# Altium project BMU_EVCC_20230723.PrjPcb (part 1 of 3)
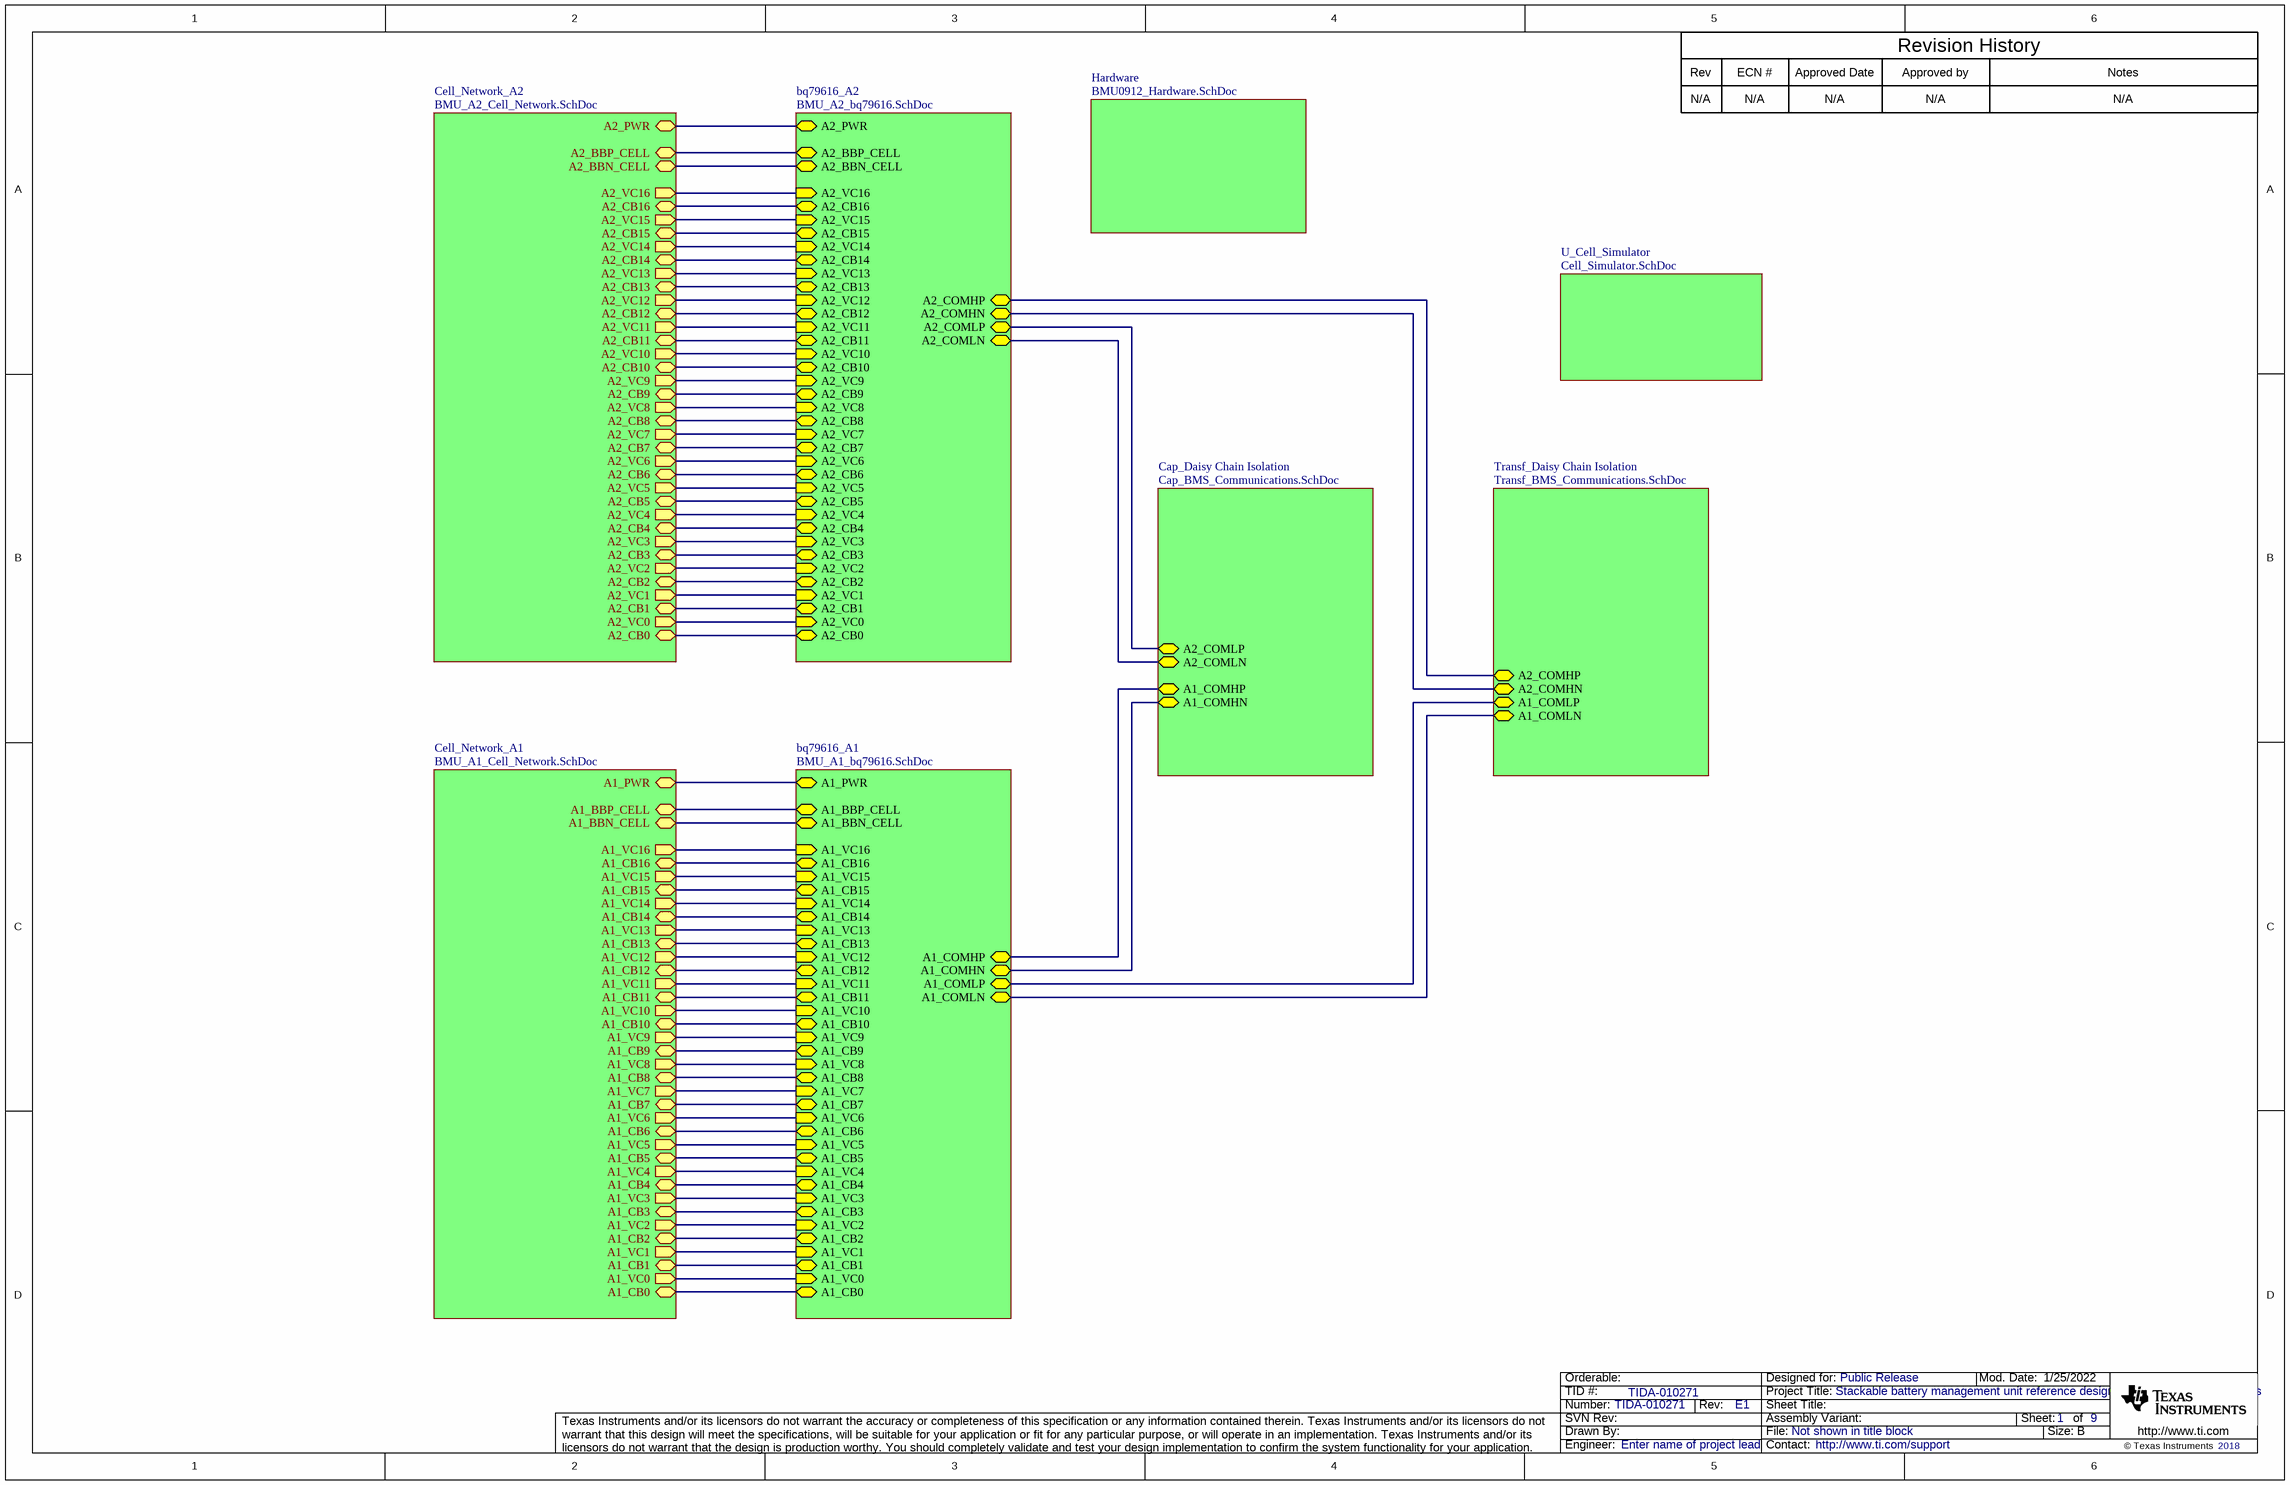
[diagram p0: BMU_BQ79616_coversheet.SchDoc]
CopyrightYear: 2018; PCB_Layout: Junhua Yan; PCB_Rev: E1; PRJ_Customer: Public Release; PRJ_Engineer: Enter name of project lead; PRJ_Number: TIDA-010271; PRJ_Title: Stackable battery management unit reference design for energy storage systems; SCH_Rev: E1; TechSupport: http://www.ti.com/support; TID: TIDA-010271
9 sheets, 713 parts. Net scope: hierarchical (ports join the sheet entries above them; power ports are global).
Board file: BMU_BQ79616.PcbDoc
Sheets:
  BMU_BQ79616_coversheet.SchDoc
    Cell_Network_A2 = BMU_A2_Cell_Network.SchDoc
    bq79616_A2 = BMU_A2_bq79616.SchDoc
    Transf_Daisy Chain Isolation = Transf_BMS_Communications.SchDoc
    Cap_Daisy Chain Isolation = Cap_BMS_Communications.SchDoc
    Cell_Network_A1 = BMU_A1_Cell_Network.SchDoc
    bq79616_A1 = BMU_A1_bq79616.SchDoc
    Hardware = BMU0912_Hardware.SchDoc
    U_Cell_Simulator = Cell_Simulator.SchDoc

## Sheet BMU_BQ79616_coversheet.SchDoc
size 431 x 279 mm; Date: Not shown in title block; ApprovedBy: Not shown in title block; CheckedBy: Not shown in title block; Author: Not shown in title block; CompanyName: Not shown in title block; Engineer: Not shown in title block; Organization: Not shown in title block; Address1: Not shown in title block; Address2: Not shown in title block; Address3: Not shown in title block; Address4: Not shown in title block; DocumentNumber: 1; Revision: Use project parameter SCH_Rev; SheetNumber: 1; SheetTotal: 9; PageSetup: Record=PageOptions¦CenterHorizontal=True¦CenterVertical=True¦PrintScale=1.00¦XCorrection=1.00¦YCorrection=1.00¦PrintKind=0¦BorderSize=5000000¦LeftOffset=0¦BottomOffset=0¦Orientation=2¦PaperLength=1000¦PaperWidth=1000¦Scale=100¦PaperSource=15¦PrintQuality=600¦MediaType=1¦DitherType=10¦PaperKind=Letter¦PrintScaleMode=1

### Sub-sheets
bq79616_A1 = BMU_A1_bq79616.SchDoc: A1_PWR (bidir), A1_CB1 (bidir), A1_CB14 (bidir), A1_CB15 (bidir), A1_CB16 (bidir), A1_VC0 (in), A1_VC1 (in), A1_VC2 (in), A1_VC3 (in), A1_VC4 (in), A1_VC5 (in), A1_VC6 (in), A1_VC7 (in), A1_VC8 (in), A1_VC9 (in), A1_VC10 (in), A1_VC11 (in), A1_VC12 (in), A1_VC13 (in), A1_VC14 (in), A1_VC15 (in), A1_VC16 (in), A1_CB2 (bidir), A1_CB3 (bidir), A1_CB4 (bidir), A1_CB5 (bidir), A1_CB6 (bidir), A1_CB7 (bidir), A1_CB8 (bidir), A1_CB9 (bidir), A1_CB10 (bidir), A1_CB11 (bidir), A1_CB12 (bidir), A1_CB13 (bidir), A1_COMLN (bidir), A1_COMLP (bidir), A1_COMHN (bidir), A1_COMHP (bidir), A1_CB0 (bidir), A1_BBP_CELL (bidir), A1_BBN_CELL (bidir)
bq79616_A2 = BMU_A2_bq79616.SchDoc: A2_PWR (bidir), A2_CB1 (bidir), A2_CB14 (bidir), A2_CB15 (bidir), A2_CB16 (bidir), A2_VC0 (in), A2_VC1 (in), A2_VC2 (in), A2_VC3 (in), A2_VC4 (in), A2_VC5 (in), A2_VC6 (in), A2_VC7 (in), A2_VC8 (in), A2_VC9 (in), A2_VC10 (in), A2_VC11 (in), A2_VC12 (in), A2_VC13 (in), A2_VC14 (in), A2_VC15 (in), A2_VC16 (in), A2_CB2 (bidir), A2_CB3 (bidir), A2_CB4 (bidir), A2_CB5 (bidir), A2_CB6 (bidir), A2_CB7 (bidir), A2_CB8 (bidir), A2_CB9 (bidir), A2_CB10 (bidir), A2_CB11 (bidir), A2_CB12 (bidir), A2_CB13 (bidir), A2_COMLN (bidir), A2_COMLP (bidir), A2_COMHN (bidir), A2_COMHP (bidir), A2_CB0 (bidir), A2_BBP_CELL (bidir), A2_BBN_CELL (bidir)
Cap_Daisy Chain Isolation = Cap_BMS_Communications.SchDoc: A2_COMLP (bidir), A1_COMHN (bidir), A2_COMLN (bidir), A1_COMHP (bidir)
Cell_Network_A1 = BMU_A1_Cell_Network.SchDoc: A1_PWR (bidir), A1_VC16 (out), A1_CB16 (bidir), A1_VC15 (out), A1_CB15 (bidir), A1_VC14 (out), A1_CB14 (bidir), A1_VC13 (out), A1_CB13 (bidir), A1_VC12 (out), A1_CB12 (bidir), A1_VC11 (out), A1_CB11 (bidir), A1_VC10 (out), A1_CB10 (bidir), A1_VC9 (out), A1_CB9 (bidir), A1_VC8 (out), A1_CB8 (bidir), A1_VC7 (out), A1_CB7 (bidir), A1_VC6 (out), A1_CB6 (bidir), A1_VC5 (out), A1_CB5 (bidir), A1_VC4 (out), A1_CB4 (bidir), A1_VC3 (out), A1_CB3 (bidir), A1_VC2 (out), A1_CB2 (bidir), A1_VC1 (out), A1_CB1 (bidir), A1_VC0 (out), A1_CB0 (bidir), A1_BBN_CELL (bidir), A1_BBP_CELL (bidir)
Cell_Network_A2 = BMU_A2_Cell_Network.SchDoc: A2_PWR (bidir), A2_VC16 (out), A2_CB16 (bidir), A2_VC15 (out), A2_CB15 (bidir), A2_VC14 (out), A2_CB14 (bidir), A2_VC13 (out), A2_CB13 (bidir), A2_VC12 (out), A2_CB12 (bidir), A2_VC11 (out), A2_CB11 (bidir), A2_VC10 (out), A2_CB10 (bidir), A2_VC9 (out), A2_CB9 (bidir), A2_VC8 (out), A2_CB8 (bidir), A2_VC7 (out), A2_CB7 (bidir), A2_VC6 (out), A2_CB6 (bidir), A2_VC5 (out), A2_CB5 (bidir), A2_VC4 (out), A2_CB4 (bidir), A2_VC3 (out), A2_CB3 (bidir), A2_VC2 (out), A2_CB2 (bidir), A2_VC1 (out), A2_CB1 (bidir), A2_VC0 (out), A2_CB0 (bidir), A2_BBP_CELL (bidir), A2_BBN_CELL (bidir)
Hardware = BMU0912_Hardware.SchDoc: no entries
Transf_Daisy Chain Isolation = Transf_BMS_Communications.SchDoc: A1_COMLP (bidir), A2_COMHN (bidir), A1_COMLN (bidir), A2_COMHP (bidir)
U_Cell_Simulator = Cell_Simulator.SchDoc: no entries

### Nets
A1_BBN_CELL: sheet Cell_Network_A1/A1_BBN_CELL, sheet bq79616_A1/A1_BBN_CELL
A1_BBP_CELL: sheet Cell_Network_A1/A1_BBP_CELL, sheet bq79616_A1/A1_BBP_CELL
A1_CB0: sheet Cell_Network_A1/A1_CB0, sheet bq79616_A1/A1_CB0
A1_CB1: sheet Cell_Network_A1/A1_CB1, sheet bq79616_A1/A1_CB1
A1_CB2: sheet Cell_Network_A1/A1_CB2, sheet bq79616_A1/A1_CB2
A1_CB3: sheet Cell_Network_A1/A1_CB3, sheet bq79616_A1/A1_CB3
A1_CB4: sheet Cell_Network_A1/A1_CB4, sheet bq79616_A1/A1_CB4
A1_CB5: sheet Cell_Network_A1/A1_CB5, sheet bq79616_A1/A1_CB5
A1_CB6: sheet Cell_Network_A1/A1_CB6, sheet bq79616_A1/A1_CB6
A1_CB7: sheet Cell_Network_A1/A1_CB7, sheet bq79616_A1/A1_CB7
A1_CB8: sheet Cell_Network_A1/A1_CB8, sheet bq79616_A1/A1_CB8
A1_CB9: sheet Cell_Network_A1/A1_CB9, sheet bq79616_A1/A1_CB9
A1_CB10: sheet Cell_Network_A1/A1_CB10, sheet bq79616_A1/A1_CB10
A1_CB11: sheet Cell_Network_A1/A1_CB11, sheet bq79616_A1/A1_CB11
A1_CB12: sheet Cell_Network_A1/A1_CB12, sheet bq79616_A1/A1_CB12
A1_CB13: sheet Cell_Network_A1/A1_CB13, sheet bq79616_A1/A1_CB13
A1_CB14: sheet Cell_Network_A1/A1_CB14, sheet bq79616_A1/A1_CB14
A1_CB15: sheet Cell_Network_A1/A1_CB15, sheet bq79616_A1/A1_CB15
A1_CB16: sheet Cell_Network_A1/A1_CB16, sheet bq79616_A1/A1_CB16
A1_COMHN: sheet Cap_Daisy Chain Isolation/A1_COMHN, sheet bq79616_A1/A1_COMHN
A1_COMHP: sheet Cap_Daisy Chain Isolation/A1_COMHP, sheet bq79616_A1/A1_COMHP
A1_COMLN: sheet Transf_Daisy Chain Isolation/A1_COMLN, sheet bq79616_A1/A1_COMLN
A1_COMLP: sheet Transf_Daisy Chain Isolation/A1_COMLP, sheet bq79616_A1/A1_COMLP
A1_PWR: sheet Cell_Network_A1/A1_PWR, sheet bq79616_A1/A1_PWR
A1_VC0: sheet Cell_Network_A1/A1_VC0, sheet bq79616_A1/A1_VC0
A1_VC1: sheet Cell_Network_A1/A1_VC1, sheet bq79616_A1/A1_VC1
A1_VC2: sheet Cell_Network_A1/A1_VC2, sheet bq79616_A1/A1_VC2
A1_VC3: sheet Cell_Network_A1/A1_VC3, sheet bq79616_A1/A1_VC3
A1_VC4: sheet Cell_Network_A1/A1_VC4, sheet bq79616_A1/A1_VC4
A1_VC5: sheet Cell_Network_A1/A1_VC5, sheet bq79616_A1/A1_VC5
A1_VC6: sheet Cell_Network_A1/A1_VC6, sheet bq79616_A1/A1_VC6
A1_VC7: sheet Cell_Network_A1/A1_VC7, sheet bq79616_A1/A1_VC7
A1_VC8: sheet Cell_Network_A1/A1_VC8, sheet bq79616_A1/A1_VC8
A1_VC9: sheet Cell_Network_A1/A1_VC9, sheet bq79616_A1/A1_VC9
A1_VC10: sheet Cell_Network_A1/A1_VC10, sheet bq79616_A1/A1_VC10
A1_VC11: sheet Cell_Network_A1/A1_VC11, sheet bq79616_A1/A1_VC11
A1_VC12: sheet Cell_Network_A1/A1_VC12, sheet bq79616_A1/A1_VC12
A1_VC13: sheet Cell_Network_A1/A1_VC13, sheet bq79616_A1/A1_VC13
A1_VC14: sheet Cell_Network_A1/A1_VC14, sheet bq79616_A1/A1_VC14
A1_VC15: sheet Cell_Network_A1/A1_VC15, sheet bq79616_A1/A1_VC15
A1_VC16: sheet Cell_Network_A1/A1_VC16, sheet bq79616_A1/A1_VC16
A2_BBN_CELL: sheet Cell_Network_A2/A2_BBN_CELL, sheet bq79616_A2/A2_BBN_CELL
A2_BBP_CELL: sheet Cell_Network_A2/A2_BBP_CELL, sheet bq79616_A2/A2_BBP_CELL
A2_CB0: sheet Cell_Network_A2/A2_CB0, sheet bq79616_A2/A2_CB0
A2_CB1: sheet Cell_Network_A2/A2_CB1, sheet bq79616_A2/A2_CB1
A2_CB2: sheet Cell_Network_A2/A2_CB2, sheet bq79616_A2/A2_CB2
A2_CB3: sheet Cell_Network_A2/A2_CB3, sheet bq79616_A2/A2_CB3
A2_CB4: sheet Cell_Network_A2/A2_CB4, sheet bq79616_A2/A2_CB4
A2_CB5: sheet Cell_Network_A2/A2_CB5, sheet bq79616_A2/A2_CB5
A2_CB6: sheet Cell_Network_A2/A2_CB6, sheet bq79616_A2/A2_CB6
A2_CB7: sheet Cell_Network_A2/A2_CB7, sheet bq79616_A2/A2_CB7
A2_CB8: sheet Cell_Network_A2/A2_CB8, sheet bq79616_A2/A2_CB8
A2_CB9: sheet Cell_Network_A2/A2_CB9, sheet bq79616_A2/A2_CB9
A2_CB10: sheet Cell_Network_A2/A2_CB10, sheet bq79616_A2/A2_CB10
A2_CB11: sheet Cell_Network_A2/A2_CB11, sheet bq79616_A2/A2_CB11
A2_CB12: sheet Cell_Network_A2/A2_CB12, sheet bq79616_A2/A2_CB12
A2_CB13: sheet Cell_Network_A2/A2_CB13, sheet bq79616_A2/A2_CB13
A2_CB14: sheet Cell_Network_A2/A2_CB14, sheet bq79616_A2/A2_CB14
A2_CB15: sheet Cell_Network_A2/A2_CB15, sheet bq79616_A2/A2_CB15
A2_CB16: sheet Cell_Network_A2/A2_CB16, sheet bq79616_A2/A2_CB16
A2_COMHN: sheet bq79616_A2/A2_COMHN, sheet Transf_Daisy Chain Isolation/A2_COMHN
A2_COMHP: sheet bq79616_A2/A2_COMHP, sheet Transf_Daisy Chain Isolation/A2_COMHP
A2_COMLN: sheet bq79616_A2/A2_COMLN, sheet Cap_Daisy Chain Isolation/A2_COMLN
A2_COMLP: sheet bq79616_A2/A2_COMLP, sheet Cap_Daisy Chain Isolation/A2_COMLP
A2_PWR: sheet Cell_Network_A2/A2_PWR, sheet bq79616_A2/A2_PWR
A2_VC0: sheet Cell_Network_A2/A2_VC0, sheet bq79616_A2/A2_VC0
A2_VC1: sheet Cell_Network_A2/A2_VC1, sheet bq79616_A2/A2_VC1
A2_VC2: sheet Cell_Network_A2/A2_VC2, sheet bq79616_A2/A2_VC2
A2_VC3: sheet Cell_Network_A2/A2_VC3, sheet bq79616_A2/A2_VC3
A2_VC4: sheet Cell_Network_A2/A2_VC4, sheet bq79616_A2/A2_VC4
A2_VC5: sheet Cell_Network_A2/A2_VC5, sheet bq79616_A2/A2_VC5
A2_VC6: sheet Cell_Network_A2/A2_VC6, sheet bq79616_A2/A2_VC6
A2_VC7: sheet Cell_Network_A2/A2_VC7, sheet bq79616_A2/A2_VC7
A2_VC8: sheet Cell_Network_A2/A2_VC8, sheet bq79616_A2/A2_VC8
A2_VC9: sheet Cell_Network_A2/A2_VC9, sheet bq79616_A2/A2_VC9
A2_VC10: sheet Cell_Network_A2/A2_VC10, sheet bq79616_A2/A2_VC10
A2_VC11: sheet Cell_Network_A2/A2_VC11, sheet bq79616_A2/A2_VC11
A2_VC12: sheet Cell_Network_A2/A2_VC12, sheet bq79616_A2/A2_VC12
A2_VC13: sheet Cell_Network_A2/A2_VC13, sheet bq79616_A2/A2_VC13
A2_VC14: sheet Cell_Network_A2/A2_VC14, sheet bq79616_A2/A2_VC14
A2_VC15: sheet Cell_Network_A2/A2_VC15, sheet bq79616_A2/A2_VC15
A2_VC16: sheet Cell_Network_A2/A2_VC16, sheet bq79616_A2/A2_VC16

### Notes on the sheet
- Rev
- N/A
- ECN #
- Approved Date
- Approved by
- Revision History
- Notes

## Sheet BMU_A2_Cell_Network.SchDoc
size C; SheetNumber: 3; SheetTotal: 9
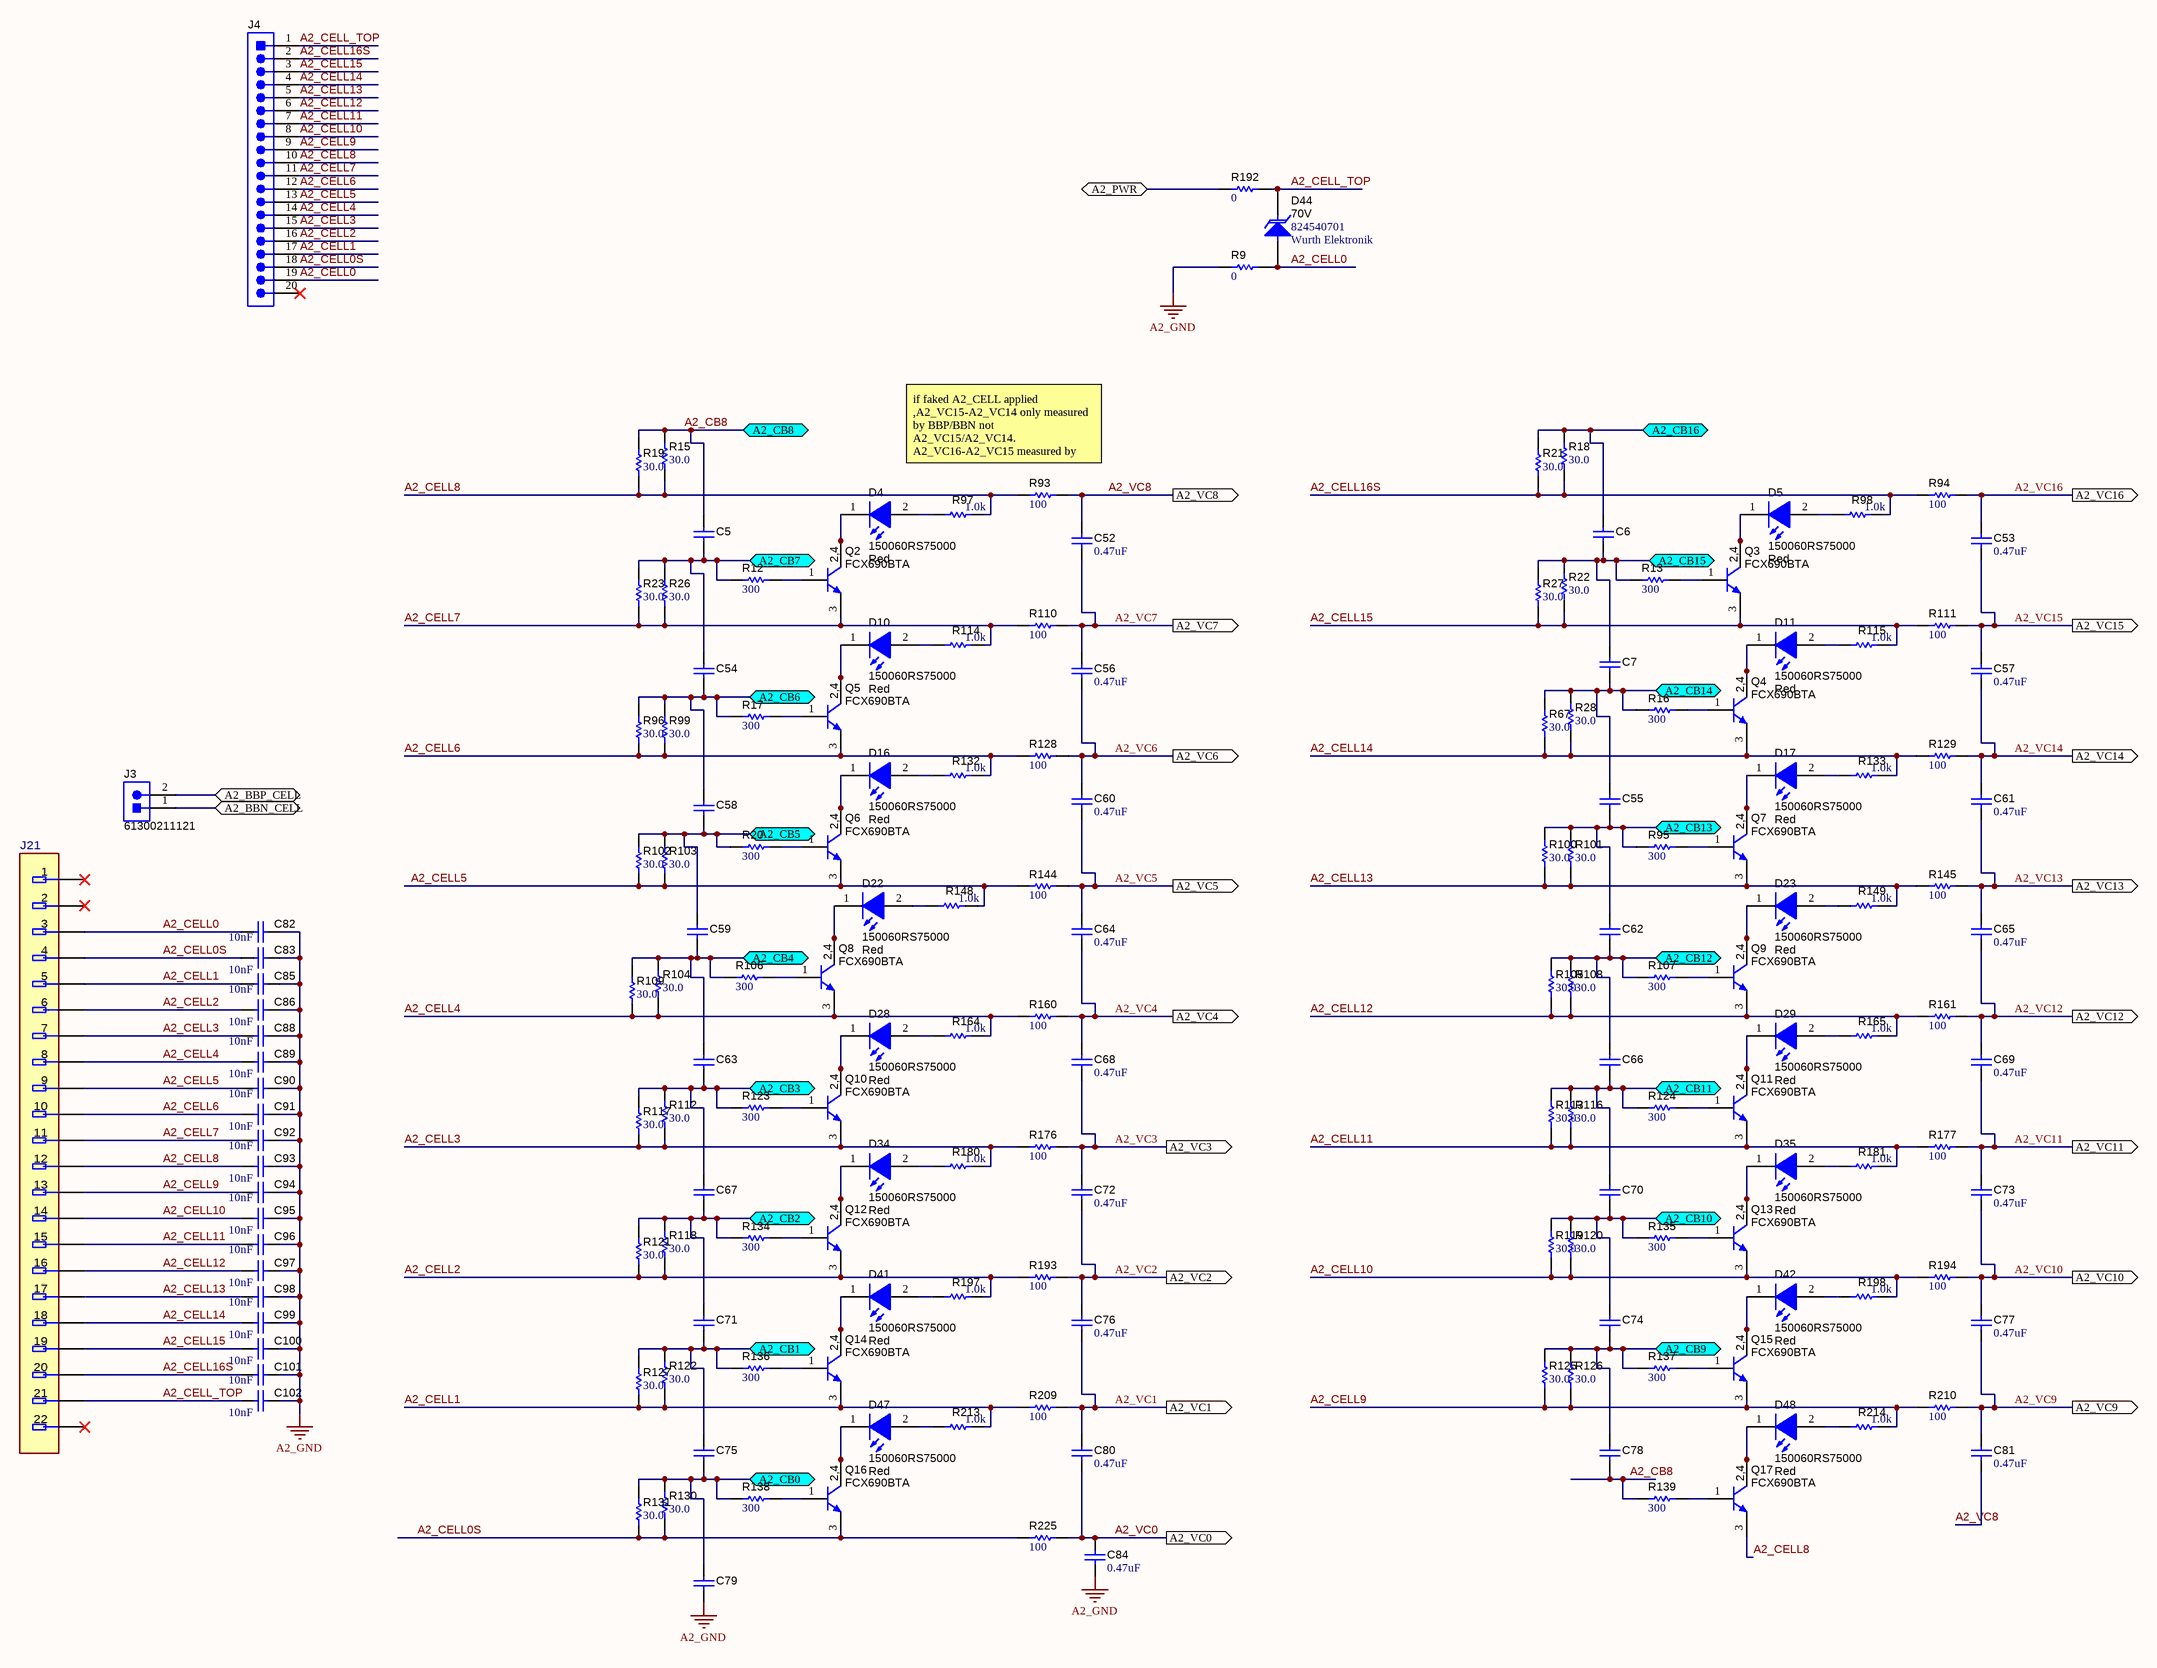
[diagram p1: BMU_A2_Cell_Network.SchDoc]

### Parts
C5  GCM188R71C474KA55D  [0603]  (value not drawn)
C6  GCM188R71C474KA55D  [0603]  (value not drawn)
C7  GCM188R71C474KA55D  [0603]  (value not drawn)
C52  ValueDisplayed: 0.47uF  [0603]  (hidden comment: GCM188R71C474KA55D)
C53  ValueDisplayed: 0.47uF  [0603]  (hidden comment: GCM188R71C474KA55D)
C54  GCM188R71C474KA55D  [0603]  (value not drawn)
C55  GCM188R71C474KA55D  [0603]  (value not drawn)
C56  ValueDisplayed: 0.47uF  [0603]  (hidden comment: GCM188R71C474KA55D)
C57  ValueDisplayed: 0.47uF  [0603]  (hidden comment: GCM188R71C474KA55D)
C58  GCM188R71C474KA55D  [0603]  (value not drawn)
C59  GCM188R71C474KA55D  [0603]  (value not drawn)
C60  ValueDisplayed: 0.47uF  [0603]  (hidden comment: GCM188R71C474KA55D)
C61  ValueDisplayed: 0.47uF  [0603]  (hidden comment: GCM188R71C474KA55D)
C62  GCM188R71C474KA55D  [0603]  (value not drawn)
C63  GCM188R71C474KA55D  [0603]  (value not drawn)
C64  ValueDisplayed: 0.47uF  [0603]  (hidden comment: GCM188R71C474KA55D)
C65  ValueDisplayed: 0.47uF  [0603]  (hidden comment: GCM188R71C474KA55D)
C66  GCM188R71C474KA55D  [0603]  (value not drawn)
C67  GCM188R71C474KA55D  [0603]  (value not drawn)
C68  ValueDisplayed: 0.47uF  [0603]  (hidden comment: GCM188R71C474KA55D)
C69  ValueDisplayed: 0.47uF  [0603]  (hidden comment: GCM188R71C474KA55D)
C70  GCM188R71C474KA55D  [0603]  (value not drawn)
C71  GCM188R71C474KA55D  [0603]  (value not drawn)
C72  ValueDisplayed: 0.47uF  [0603]  (hidden comment: GCM188R71C474KA55D)
C73  ValueDisplayed: 0.47uF  [0603]  (hidden comment: GCM188R71C474KA55D)
C74  GCM188R71C474KA55D  [0603]  (value not drawn)
C75  GCM188R71C474KA55D  [0603]  (value not drawn)
C76  ValueDisplayed: 0.47uF  [0603]  (hidden comment: GCM188R71C474KA55D)
C77  ValueDisplayed: 0.47uF  [0603]  (hidden comment: GCM188R71C474KA55D)
C78  GCM188R71C474KA55D  [0603]  (value not drawn)
C79  GCM188R71C474KA55D  [0603]  (value not drawn)
C80  ValueDisplayed: 0.47uF  [0603]  (hidden comment: GCM188R71C474KA55D)
C81  ValueDisplayed: 0.47uF  [0603]  (hidden comment: GCM188R71C474KA55D)
C82  Cap_F: 10nF  [0603]  (hidden comment: 885012206114)
C83  Cap_F: 10nF  [0603]  (hidden comment: 885012206114)
C84  ValueDisplayed: 0.47uF  [0603]  (hidden comment: GCM188R71C474KA55D)
C85  Cap_F: 10nF  [0603]  (hidden comment: 885012206114)
C86  Cap_F: 10nF  [0603]  (hidden comment: 885012206114)
C88  Cap_F: 10nF  [0603]  (hidden comment: 885012206114)
C89  Cap_F: 10nF  [0603]  (hidden comment: 885012206114)
C90  Cap_F: 10nF  [0603]  (hidden comment: 885012206114)
C91  Cap_F: 10nF  [0603]  (hidden comment: 885012206114)
C92  Cap_F: 10nF  [0603]  (hidden comment: 885012206114)
C93  Cap_F: 10nF  [0603]  (hidden comment: 885012206114)
C94  Cap_F: 10nF  [0603]  (hidden comment: 885012206114)
C95  Cap_F: 10nF  [0603]  (hidden comment: 885012206114)
C96  Cap_F: 10nF  [0603]  (hidden comment: 885012206114)
C97  Cap_F: 10nF  [0603]  (hidden comment: 885012206114)
C98  Cap_F: 10nF  [0603]  (hidden comment: 885012206114)
C99  Cap_F: 10nF  [0603]  (hidden comment: 885012206114)
C100  Cap_F: 10nF  [0603]  (hidden comment: 885012206114)
C101  Cap_F: 10nF  [0603]  (hidden comment: 885012206114)
C102  Cap_F: 10nF  [0603]  (hidden comment: 885012206114)
D4  150060RS75000  value Red  [WL-SMCW_RED]
D5  150060RS75000  value Red  [WL-SMCW_RED]
D10  150060RS75000  value Red  [WL-SMCW_RED]
D11  150060RS75000  value Red  [WL-SMCW_RED]
D16  150060RS75000  value Red  [WL-SMCW_RED]
D17  150060RS75000  value Red  [WL-SMCW_RED]
D22  150060RS75000  value Red  [WL-SMCW_RED]
D23  150060RS75000  value Red  [WL-SMCW_RED]
D28  150060RS75000  value Red  [WL-SMCW_RED]
D29  150060RS75000  value Red  [WL-SMCW_RED]
D34  150060RS75000  value Red  [WL-SMCW_RED]
D35  150060RS75000  value Red  [WL-SMCW_RED]
D41  150060RS75000  value Red  [WL-SMCW_RED]
D42  150060RS75000  value Red  [WL-SMCW_RED]
D44  value 70V  PartNumber: 824540701  Manufacturer: Wurth Elektronik  [SMC_265]  (hidden comment: SMCJ70A)
D47  150060RS75000  value Red  [WL-SMCW_RED]
D48  150060RS75000  value Red  [WL-SMCW_RED]
J3  61300211121  [WURTH_61300211121]
J4  TSW-120-07-G-S  [TSW-120-07-G-S]  (value not drawn)
J21  705550056  [FP-705550056_HDR22-MFG]  (value not drawn)
Q2  FCX690BTA  [SOT-89-3]
Q3  FCX690BTA  [SOT-89-3]
Q4  FCX690BTA  [SOT-89-3]
Q5  FCX690BTA  [SOT-89-3]
Q6  FCX690BTA  [SOT-89-3]
Q7  FCX690BTA  [SOT-89-3]
Q8  FCX690BTA  [SOT-89-3]
Q9  FCX690BTA  [SOT-89-3]
Q10  FCX690BTA  [SOT-89-3]
Q11  FCX690BTA  [SOT-89-3]
Q12  FCX690BTA  [SOT-89-3]
Q13  FCX690BTA  [SOT-89-3]
Q14  FCX690BTA  [SOT-89-3]
Q15  FCX690BTA  [SOT-89-3]
Q16  FCX690BTA  [SOT-89-3]
Q17  FCX690BTA  [SOT-89-3]
R9  ValueDisplayed: 0  [0603]  (hidden comment: CRCW06030000Z0EA)
R12  ValueDisplayed: 300  [0402]  (hidden comment: CRCW0402300RJNED)
R13  ValueDisplayed: 300  [0402]  (hidden comment: CRCW0402300RJNED)
R15  ValueDisplayed: 30.0  [1210]  (hidden comment: RC1210FR-0730RL)
R16  ValueDisplayed: 300  [0402]  (hidden comment: CRCW0402300RJNED)
R17  ValueDisplayed: 300  [0402]  (hidden comment: CRCW0402300RJNED)
R18  ValueDisplayed: 30.0  [1210]  (hidden comment: RC1210FR-0730RL)
R19  ValueDisplayed: 30.0  [1210]  (hidden comment: RC1210FR-0730RL)
R20  ValueDisplayed: 300  [0402]  (hidden comment: CRCW0402300RJNED)
R21  ValueDisplayed: 30.0  [1210]  (hidden comment: RC1210FR-0730RL)
R22  ValueDisplayed: 30.0  [1210]  (hidden comment: RC1210FR-0730RL)
R23  ValueDisplayed: 30.0  [1210]  (hidden comment: RC1210FR-0730RL)
R26  ValueDisplayed: 30.0  [1210]  (hidden comment: RC1210FR-0730RL)
R27  ValueDisplayed: 30.0  [1210]  (hidden comment: RC1210FR-0730RL)
R28  ValueDisplayed: 30.0  [1210]  (hidden comment: RC1210FR-0730RL)
R67  ValueDisplayed: 30.0  [1210]  (hidden comment: RC1210FR-0730RL)
R93  ValueDisplayed: 100  [0603]  (hidden comment: ERA-3AEB101V)
R94  ValueDisplayed: 100  [0603]  (hidden comment: ERA-3AEB101V)
R95  ValueDisplayed: 300  [0402]  (hidden comment: CRCW0402300RJNED)
R96  ValueDisplayed: 30.0  [1210]  (hidden comment: RC1210FR-0730RL)
R97  ValueDisplayed: 1.0k  [0603]  (hidden comment: CRCW06031K00JNEA)
R98  ValueDisplayed: 1.0k  [0603]  (hidden comment: CRCW06031K00JNEA)
R99  ValueDisplayed: 30.0  [1210]  (hidden comment: RC1210FR-0730RL)
R100  ValueDisplayed: 30.0  [1210]  (hidden comment: RC1210FR-0730RL)
R101  ValueDisplayed: 30.0  [1210]  (hidden comment: RC1210FR-0730RL)
R102  ValueDisplayed: 30.0  [1210]  (hidden comment: RC1210FR-0730RL)
R103  ValueDisplayed: 30.0  [1210]  (hidden comment: RC1210FR-0730RL)
R104  ValueDisplayed: 30.0  [1210]  (hidden comment: RC1210FR-0730RL)
R105  ValueDisplayed: 30.0  [1210]  (hidden comment: RC1210FR-0730RL)
R106  ValueDisplayed: 300  [0402]  (hidden comment: CRCW0402300RJNED)
R107  ValueDisplayed: 300  [0402]  (hidden comment: CRCW0402300RJNED)
R108  ValueDisplayed: 30.0  [1210]  (hidden comment: RC1210FR-0730RL)
R109  ValueDisplayed: 30.0  [1210]  (hidden comment: RC1210FR-0730RL)
R110  ValueDisplayed: 100  [0603]  (hidden comment: ERA-3AEB101V)
R111  ValueDisplayed: 100  [0603]  (hidden comment: ERA-3AEB101V)
R112  ValueDisplayed: 30.0  [1210]  (hidden comment: RC1210FR-0730RL)
R113  ValueDisplayed: 30.0  [1210]  (hidden comment: RC1210FR-0730RL)
R114  ValueDisplayed: 1.0k  [0603]  (hidden comment: CRCW06031K00JNEA)
R115  ValueDisplayed: 1.0k  [0603]  (hidden comment: CRCW06031K00JNEA)
R116  ValueDisplayed: 30.0  [1210]  (hidden comment: RC1210FR-0730RL)
R117  ValueDisplayed: 30.0  [1210]  (hidden comment: RC1210FR-0730RL)
R118  ValueDisplayed: 30.0  [1210]  (hidden comment: RC1210FR-0730RL)
R119  ValueDisplayed: 30.0  [1210]  (hidden comment: RC1210FR-0730RL)
R120  ValueDisplayed: 30.0  [1210]  (hidden comment: RC1210FR-0730RL)
R121  ValueDisplayed: 30.0  [1210]  (hidden comment: RC1210FR-0730RL)
R122  ValueDisplayed: 30.0  [1210]  (hidden comment: RC1210FR-0730RL)
R123  ValueDisplayed: 300  [0402]  (hidden comment: CRCW0402300RJNED)
R124  ValueDisplayed: 300  [0402]  (hidden comment: CRCW0402300RJNED)
R125  ValueDisplayed: 30.0  [1210]  (hidden comment: RC1210FR-0730RL)
R126  ValueDisplayed: 30.0  [1210]  (hidden comment: RC1210FR-0730RL)
R127  ValueDisplayed: 30.0  [1210]  (hidden comment: RC1210FR-0730RL)
R128  ValueDisplayed: 100  [0603]  (hidden comment: ERA-3AEB101V)
R129  ValueDisplayed: 100  [0603]  (hidden comment: ERA-3AEB101V)
R130  ValueDisplayed: 30.0  [1210]  (hidden comment: RC1210FR-0730RL)
R131  ValueDisplayed: 30.0  [1210]  (hidden comment: RC1210FR-0730RL)
R132  ValueDisplayed: 1.0k  [0603]  (hidden comment: CRCW06031K00JNEA)
R133  ValueDisplayed: 1.0k  [0603]  (hidden comment: CRCW06031K00JNEA)
R134  ValueDisplayed: 300  [0402]  (hidden comment: CRCW0402300RJNED)
R135  ValueDisplayed: 300  [0402]  (hidden comment: CRCW0402300RJNED)
R136  ValueDisplayed: 300  [0402]  (hidden comment: CRCW0402300RJNED)
R137  ValueDisplayed: 300  [0402]  (hidden comment: CRCW0402300RJNED)
R138  ValueDisplayed: 300  [0402]  (hidden comment: CRCW0402300RJNED)
R139  ValueDisplayed: 300  [0402]  (hidden comment: CRCW0402300RJNED)
R144  ValueDisplayed: 100  [0603]  (hidden comment: ERA-3AEB101V)
R145  ValueDisplayed: 100  [0603]  (hidden comment: ERA-3AEB101V)
R148  ValueDisplayed: 1.0k  [0603]  (hidden comment: CRCW06031K00JNEA)
R149  ValueDisplayed: 1.0k  [0603]  (hidden comment: CRCW06031K00JNEA)
R160  ValueDisplayed: 100  [0603]  (hidden comment: ERA-3AEB101V)
R161  ValueDisplayed: 100  [0603]  (hidden comment: ERA-3AEB101V)
R164  ValueDisplayed: 1.0k  [0603]  (hidden comment: CRCW06031K00JNEA)
R165  ValueDisplayed: 1.0k  [0603]  (hidden comment: CRCW06031K00JNEA)
R176  ValueDisplayed: 100  [0603]  (hidden comment: ERA-3AEB101V)
R177  ValueDisplayed: 100  [0603]  (hidden comment: ERA-3AEB101V)
R180  ValueDisplayed: 1.0k  [0603]  (hidden comment: CRCW06031K00JNEA)
R181  ValueDisplayed: 1.0k  [0603]  (hidden comment: CRCW06031K00JNEA)
R192  ValueDisplayed: 0  [0603]  (hidden comment: CRCW06030000Z0EA)
R193  ValueDisplayed: 100  [0603]  (hidden comment: ERA-3AEB101V)
R194  ValueDisplayed: 100  [0603]  (hidden comment: ERA-3AEB101V)
R197  ValueDisplayed: 1.0k  [0603]  (hidden comment: CRCW06031K00JNEA)
R198  ValueDisplayed: 1.0k  [0603]  (hidden comment: CRCW06031K00JNEA)
R209  ValueDisplayed: 100  [0603]  (hidden comment: ERA-3AEB101V)
R210  ValueDisplayed: 100  [0603]  (hidden comment: ERA-3AEB101V)
R213  ValueDisplayed: 1.0k  [0603]  (hidden comment: CRCW06031K00JNEA)
R214  ValueDisplayed: 1.0k  [0603]  (hidden comment: CRCW06031K00JNEA)
R225  ValueDisplayed: 100  [0603]  (hidden comment: ERA-3AEB101V)

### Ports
A2_BBN_CELL (bidir), A2_BBP_CELL (bidir), A2_CB0 (bidir), A2_CB1 (bidir), A2_CB2 (bidir), A2_CB3 (bidir), A2_CB4 (bidir), A2_CB5 (bidir), A2_CB6 (bidir), A2_CB7 (bidir), A2_CB8 (bidir), A2_CB9 (bidir), A2_CB10 (bidir), A2_CB11 (bidir), A2_CB12 (bidir), A2_CB13 (bidir), A2_CB14 (bidir), A2_CB15 (bidir), A2_CB16 (bidir), A2_PWR (bidir), A2_VC0 (out), A2_VC1 (out), A2_VC2 (out), A2_VC3 (out), A2_VC4 (out), A2_VC5 (out), A2_VC6 (out), A2_VC7 (out), A2_VC8 (out), A2_VC9 (out), A2_VC10 (out), A2_VC11 (out), A2_VC12 (out), A2_VC13 (out), A2_VC14 (out), A2_VC15 (out), A2_VC16 (out)

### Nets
A2_GND: C79.2 C82.2 C83.2 C84.2 C85.2 C86.2 C88.2 C89.2 C90.2 C91.2 C92.2 C93.2 C94.2 C95.2 C96.2 C97.2 C98.2 C99.2 C100.2 C101.2 C102.2 R9.1
A2_BBN_CELL: J3.1 ; port A2_BBN_CELL
A2_BBP_CELL: J3.2 ; port A2_BBP_CELL
A2_CB0: C75.2 C79.1 R130.2 R131.2 R138.1 ; port A2_CB0
A2_CB1: C71.2 C75.1 R122.2 R127.2 R136.1 ; port A2_CB1
A2_CB2: C67.2 C71.1 R118.2 R121.2 R134.1 ; port A2_CB2
A2_CB3: C63.2 C67.1 R112.2 R117.2 R123.1 ; port A2_CB3
A2_CB4: C59.2 C63.1 R104.2 R106.1 R109.2 ; port A2_CB4
A2_CB5: C58.2 C59.1 R20.1 R102.2 R103.2 ; port A2_CB5
A2_CB6: C54.2 C58.1 R17.1 R96.2 R99.2 ; port A2_CB6
A2_CB7: C5.2 C54.1 R12.1 R23.2 R26.2 ; port A2_CB7
A2_CB8: C5.1 C78.2 R15.2 R19.2 R139.1 ; port A2_CB8
A2_CB9: C74.2 C78.1 R125.2 R126.2 R137.1 ; port A2_CB9
A2_CB10: C70.2 C74.1 R119.2 R120.2 R135.1 ; port A2_CB10
A2_CB11: C66.2 C70.1 R113.2 R116.2 R124.1 ; port A2_CB11
A2_CB12: C62.2 C66.1 R105.2 R107.1 R108.2 ; port A2_CB12
A2_CB13: C55.2 C62.1 R95.1 R100.2 R101.2 ; port A2_CB13
A2_CB14: C7.2 C55.1 R16.1 R28.2 R67.2 ; port A2_CB14
A2_CB15: C6.2 C7.1 R13.1 R22.2 R27.2 ; port A2_CB15
A2_CB16: C6.1 R18.2 R21.2 ; port A2_CB16
A2_CELL0: C82.1 D44.2(A) J4.19 J21.3 R9.2
A2_CELL0S: C83.1 J4.18 J21.4 Q16.3(E) R130.1 R131.1 R225.1
A2_CELL1: C85.1 J4.17 J21.5 Q14.3(E) R122.1 R127.1 R209.1 R213.1
A2_CELL2: C86.1 J4.16 J21.6 Q12.3(E) R118.1 R121.1 R193.1 R197.1
A2_CELL3: C88.1 J4.15 J21.7 Q10.3(E) R112.1 R117.1 R176.1 R180.1
A2_CELL4: C89.1 J4.14 J21.8 Q8.3(E) R104.1 R109.1 R160.1 R164.1
A2_CELL5: C90.1 J4.13 J21.9 Q6.3(E) R102.1 R103.1 R144.1 R148.1
A2_CELL6: C91.1 J4.12 J21.10 Q5.3(E) R96.1 R99.1 R128.1 R132.1
A2_CELL7: C92.1 J4.11 J21.11 Q2.3(E) R23.1 R26.1 R110.1 R114.1
A2_CELL8: C93.1 J4.10 J21.12 Q17.3(E) R15.1 R19.1 R93.1 R97.1
A2_CELL9: C94.1 J4.9 J21.13 Q15.3(E) R125.1 R126.1 R210.1 R214.1
A2_CELL10: C95.1 J4.8 J21.14 Q13.3(E) R119.1 R120.1 R194.1 R198.1
A2_CELL11: C96.1 J4.7 J21.15 Q11.3(E) R113.1 R116.1 R177.1 R181.1
A2_CELL12: C97.1 J4.6 J21.16 Q9.3(E) R105.1 R108.1 R161.1 R165.1
A2_CELL13: C98.1 J4.5 J21.17 Q7.3(E) R100.1 R101.1 R145.1 R149.1
A2_CELL14: C99.1 J4.4 J21.18 Q4.3(E) R28.1 R67.1 R129.1 R133.1
A2_CELL15: C100.1 J4.3 J21.19 Q3.3(E) R22.1 R27.1 R111.1 R115.1
A2_CELL16S: C101.1 J4.2 J21.20 R18.1 R21.1 R94.1 R98.1
A2_CELL_TOP: C102.1 D44.1(K) J4.1 J21.21 R192.2
A2_PWR: R192.1 ; port A2_PWR
A2_VC0: C80.2 C84.1 R225.2 ; port A2_VC0
A2_VC1: C76.2 C80.1 R209.2 ; port A2_VC1
A2_VC2: C72.2 C76.1 R193.2 ; port A2_VC2
A2_VC3: C68.2 C72.1 R176.2 ; port A2_VC3
A2_VC4: C64.2 C68.1 R160.2 ; port A2_VC4
A2_VC5: C60.2 C64.1 R144.2 ; port A2_VC5
A2_VC6: C56.2 C60.1 R128.2 ; port A2_VC6
A2_VC7: C52.2 C56.1 R110.2 ; port A2_VC7
A2_VC8: C52.1 C81.2 R93.2 ; port A2_VC8
A2_VC9: C77.2 C81.1 R210.2 ; port A2_VC9
A2_VC10: C73.2 C77.1 R194.2 ; port A2_VC10
A2_VC11: C69.2 C73.1 R177.2 ; port A2_VC11
A2_VC12: C65.2 C69.1 R161.2 ; port A2_VC12
A2_VC13: C61.2 C65.1 R145.2 ; port A2_VC13
A2_VC14: C57.2 C61.1 R129.2 ; port A2_VC14
A2_VC15: C53.2 C57.1 R111.2 ; port A2_VC15
A2_VC16: C53.1 R94.2 ; port A2_VC16
NetD4_1: D4.1(K) Q2.2(C) Q2.4(C)
NetD4_2: D4.2(A) R97.2
NetD5_1: D5.1(K) Q3.2(C) Q3.4(C)
NetD5_2: D5.2(A) R98.2
NetD10_1: D10.1(K) Q5.2(C) Q5.4(C)
NetD10_2: D10.2(A) R114.2
NetD11_1: D11.1(K) Q4.2(C) Q4.4(C)
NetD11_2: D11.2(A) R115.2
NetD16_1: D16.1(K) Q6.2(C) Q6.4(C)
NetD16_2: D16.2(A) R132.2
NetD17_1: D17.1(K) Q7.2(C) Q7.4(C)
NetD17_2: D17.2(A) R133.2
NetD22_1: D22.1(K) Q8.2(C) Q8.4(C)
NetD22_2: D22.2(A) R148.2
NetD23_1: D23.1(K) Q9.2(C) Q9.4(C)
NetD23_2: D23.2(A) R149.2
NetD28_1: D28.1(K) Q10.2(C) Q10.4(C)
NetD28_2: D28.2(A) R164.2
NetD29_1: D29.1(K) Q11.2(C) Q11.4(C)
NetD29_2: D29.2(A) R165.2
NetD34_1: D34.1(K) Q12.2(C) Q12.4(C)
NetD34_2: D34.2(A) R180.2
NetD35_1: D35.1(K) Q13.2(C) Q13.4(C)
NetD35_2: D35.2(A) R181.2
NetD41_1: D41.1(K) Q14.2(C) Q14.4(C)
NetD41_2: D41.2(A) R197.2
NetD42_1: D42.1(K) Q15.2(C) Q15.4(C)
NetD42_2: D42.2(A) R198.2
NetD47_1: D47.1(K) Q16.2(C) Q16.4(C)
NetD47_2: D47.2(A) R213.2
NetD48_1: D48.1(K) Q17.2(C) Q17.4(C)
NetD48_2: D48.2(A) R214.2
NetQ2_1: Q2.1(B) R12.2
NetQ3_1: Q3.1(B) R13.2
NetQ4_1: Q4.1(B) R16.2
NetQ5_1: Q5.1(B) R17.2
NetQ6_1: Q6.1(B) R20.2
NetQ7_1: Q7.1(B) R95.2
NetQ8_1: Q8.1(B) R106.2
NetQ9_1: Q9.1(B) R107.2
NetQ10_1: Q10.1(B) R123.2
NetQ11_1: Q11.1(B) R124.2
NetQ12_1: Q12.1(B) R134.2
NetQ13_1: Q13.1(B) R135.2
NetQ14_1: Q14.1(B) R136.2
NetQ15_1: Q15.1(B) R137.2
NetQ16_1: Q16.1(B) R138.2
NetQ17_1: Q17.1(B) R139.2

Not connected (* = marked no-connect by the designer): J4 20*; J21 1* 2* 22*

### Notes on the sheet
- if faked A2_CELL applied ,A2_VC15-A2_VC14 only measured by BBP/BBN not A2_VC15/A2_VC14. A2_VC16-A2_VC15 measured by bypass resistor

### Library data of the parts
C5-C7 C52-C67 C69-C71 C73-C81 = CMP-0007138-4: CAP, CERM, 0.47 uF, 16 V, +/- 10%, X7R, AEC-Q200 Grade 1, 0603; Manufacturer: MuRata; Polarized: N; Value: 0.47uF; U/M: EA; Cap_F: 470nF; Value1: Unknown; VDC_V: 16V; TaMin_C: -55°C; TaMax_C: 125°C; AEC Category: Q200; AEC Qualified: Y; AEC Grade: 1; SizeArea_mm2: 1.28; SizeAreaWB_mm2: 4.68; SizeX_mm: 1.6; SizeY_mm: 0.8
C68 C72 C84 = CMP-0007138-4: CAP, CERM, 0.47 uF, 16 V, +/- 10%, X7R, AEC-Q200 Grade 1, 0603; Manufacturer: MuRata; Polarized: N; Value: 0.47uF; U/M: EA; Cap_F: 470nF; Value1: Unknown; VDC_V: 16V; TaMin_C: -55°C; TaMax_C: 125°C; AEC Category: Q200; AEC Qualified: Y; AEC Grade: 1; SizeAreaWB_mm2: 4.68; SizeX_mm: 1.6; SizeY_mm: 0.8; SizeArea_mm2: 1.28
C82 C83 C85 C86 C88-C102 = CMP-0079993-1: CAP, CERM, 0.01 µF, 100 V,+/- 10%, X7R, 0603; Manufacturer: Wurth Elektronik; TaMin_C: -55°C; Polarized: N; SizeAreaWB_mm2: 4.68; U/M: EA; Value: 0.01uF; TaMax_C: 105°C; SizeZ_mm: 1; SizeX_mm: 1.6; SizeY_mm: 0.8; Value2: 100V; SizeArea_mm2: 1.28; AEC Category: Q200; ValueDisplayed: 0.01µF
D4 D5 D10 D11 D16 D17 D22 D23 D28 D29 D34 D35 D41 D42 D47 D48 = CMP-0002947-3: LED, Red, SMD; Manufacturer: Wurth Elektronik; Value1: 0.072W; Vf_V: 2V; Angle: 140; Tjmax_C: 85°C; Type: AlInGaP; Vr_V: 5V; Io_A: 30mA; Power_TotalModule: 72mW
D44 = CMP-0005734-3: Diode, TVS, Uni, 70 V, 113 Vc, SMC; AEC Qualified: N; SizeAreaWB_mm2: 78.5757; SizeX_mm: 7.94; SizeArea_mm2: 46.8857; Ipp: 13.3A; RJA_CperW: 75; SizeY_mm: 5.905; Vbr_Max: 86V; SizeZ_mm: 2.62; Vbr_Min: 77.8V; Vc: 113V; Ppk: 1.5kW; AEC Category: Q101; Value1: 1500W
J3 = CMP-0054794-2: Header, 2.54 mm, 2x1, Gold, TH; Manufacturer: Wurth Elektronik; Shrouded: N; Gender: Male; Green_REACh: Passed; Pitch_mm: 2.54; Green_Lifecycle: Active; Row_Count: 1; Cert_UL: Y
J4 = CMP-0075434-1: Header, 100mil, 20x1, Gold, TH; PartNumber: 61302011121; Manufacturer: Wurth Elektronik; Pitch_mm: 2.54; Cert_VDE: N; Gender: Male; Cert_CSA: Y; Current_A: 6.3A; Voltage_V: 550V; CT: False; Row_Count: 1; CNHeader: True
J21 = CMP-0087165-1: Connector Header Through Hole, Right Angle 22 position 0.100" (2.54mm); Manufacturer: Molex; Voltage_V: 250V; Current_A: 3A; ContactFinish: Gold,Nickel; Row_Count: 1
Q2-Q17 = CMP-0000384-2: Transistor, NPN, 45 V, 1 A, SOT-89; Manufacturer: Diodes Inc.; TaMax_C: 150°C; Value1: 1 A; Vcesat1_V: 80mV; SizeX_mm: 4.1; SizeY_mm: 4.5; TaMin_C: -55°C; IcRated_A: 1A; CompType: BJT; SizeZ_mm: 1.5; Value: 45 V; SizeArea_mm2: 18.45; NPN: 1; Vceo_V: 45V; PNP: 0; AEC Category: Q101; SizeAreaWB_mm2: 28.05; U/M: EA
R9 R192 = CMP-0025697-4: RES, 0, 5%, 0.1 W, AEC-Q200 Grade 0, 0603; Manufacturer: Vishay-Dale; Power_W: 100mW; TempCo: 200 ppm/C; Value_Code: 0000; Value: 0; EIA_Code: E24; SizeX_mm: 1.6; SizeY_mm: 0.8; SizeZ_mm: 1; Value2: 0.1W; SizeArea_mm2: 1.28; AEC Qualified: Y; VDC_V: 75V; AEC Category: Q200
R12 R13 R16 R17 R20 R95 R106 R107 R123 R124 R134-R139 = CMP-0026902-3: RES, 300, 5%, 0.063 W, AEC-Q200 Grade 0, 0402; Manufacturer: Vishay-Dale; Power_W: 63mW; TempCo: 200 ppm/C; Value_Code: 300R; Value: 300; EIA_Code: E24; SizeX_mm: 1; SizeY_mm: 0.5; SizeZ_mm: 0.6; Value2: 0.063W; AEC Qualified: Y; VDC_V: 50V; AEC Category: Q200; AEC Grade: 0
R15 R18 R19 R21-R23 R26-R28 R67 R96 R99-R105 R108 R109 R112 R113 R116-R122 R125-R127 R130 R131 = CMP-0083073-1: RES, 30.0, 1%, 0.5 W, 1210; Manufacturer: Yageo; Power_W: 500mW; TempCo: 100 ppm/C; SizeAreaWB_mm2: 14.7; Value_Code: 30R0; Value: 30.0; Res_ohm: 30; SizeX_mm: 3.2; SizeY_mm: 2.5; SizeZ_mm: 1.35; Value2: 0.5W; SizeArea_mm2: 8; AEC Qualified: N; VDC_V: 200V; AEC Category: Q200
R93 R94 R110 R111 R128 R129 R144 R145 R160 R161 R176 R177 R193 R194 R209 R210 R225 = CMP-0023361-3: RES, 100, 0.1%, 0.1 W, AEC-Q200 Grade 0, 0603; Manufacturer: Panasonic; Power_W: 100mW; TempCo: 25 ppm/C; Value_Code: 100R; U/M: EA; Value: 100; EIA_Code: E192; SizeX_mm: 1.6; SizeY_mm: 0.8; SizeZ_mm: 1; Value2: 0.1W; SizeArea_mm2: 1.28; AEC Qualified: Y; VDC_V: 75V; AEC Grade: 0; AEC Category: Q200
R97 R98 R114 R115 R132 R133 R148 R149 R164 R165 R180 R181 R197 R198 R213 R214 = CMP-0025729-4: RES, 1.0 k, 5%, 0.1 W, AEC-Q200 Grade 0, 0603; Manufacturer: Vishay-Dale; Value: 1.0k; Res_ohm: 1k; Value_Code: 1k00; Power_W: 100mW; Value2: 0.1W; VDC_V: 75V; TempCo: 200 ppm/C; EIA_Code: E24; SizeArea_mm2: 1.28; SizeX_mm: 1.6; SizeY_mm: 0.8; SizeZ_mm: 1; AEC Category: Q200; AEC Qualified: Y; AEC Grade: 0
